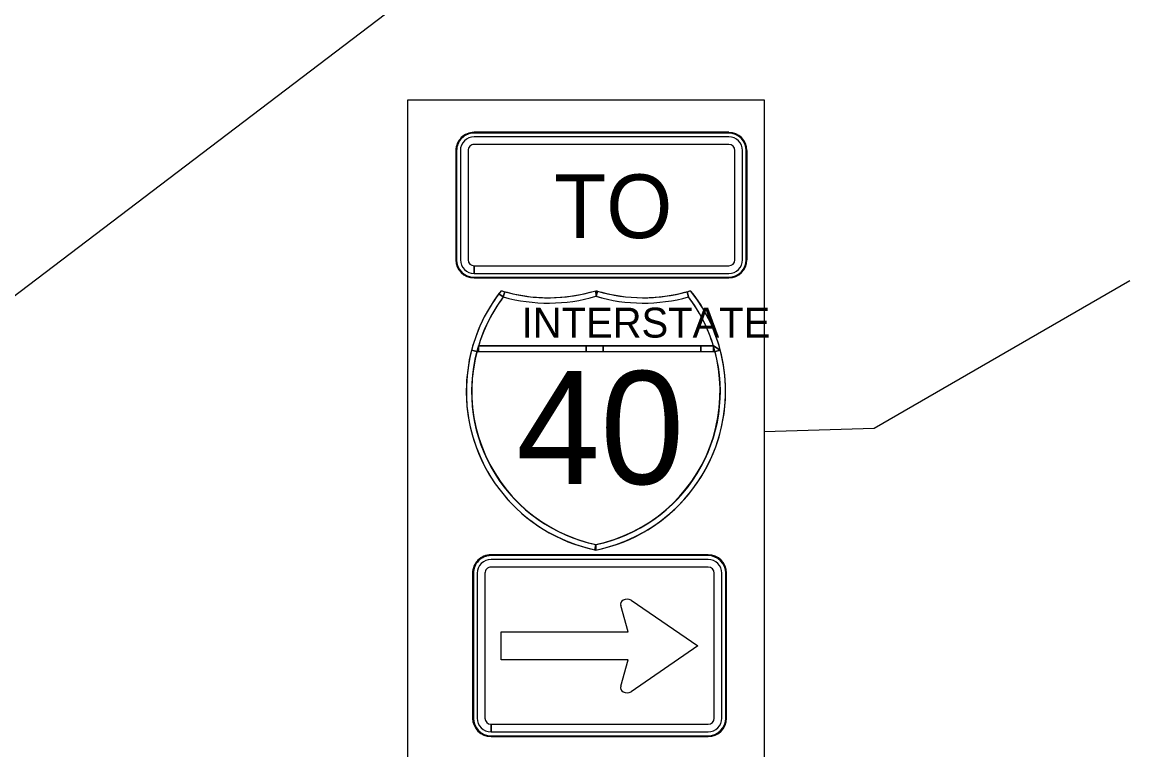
# Model space of a CAD drawing. Extents: x 886234 to 968767, y 455416 to 684046.
# Drawn here: x 914069 to 915591, y 469126 to 470126 of the extents above; entities that cross this region are included whole.
import ezdxf

# ---------------------------------------------------------------- set-up
doc = ezdxf.new("R2010")
doc.units = 0
for name, color, linetype in [('TC CONSTRUCTION PROPOSED ROADWAY SHADE', 7, 'Continuous'), ('TC DEV SIGN BLACK 239', 7, 'Continuous'), ('TC DEV SIGN BLACK ZERO', 7, 'Continuous'), ('TC DEV SIGN WHITE', 7, 'Continuous'), ('TC LABEL TEXT', 7, 'Continuous')]:
    doc.layers.add(name, color=color, linetype=linetype)

msp = doc.modelspace()

# ---------------------------------------------------------------- linework, layer by layer
at = {"layer": 'TC CONSTRUCTION PROPOSED ROADWAY SHADE'}
msp.add_lwpolyline([(914599.4, 470018.9), (915089.1, 470018.9), (915089.1, 469107.9), (914599.4, 469107.9)], close=True, dxfattribs=at)
at = {"layer": 'TC DEV SIGN BLACK 239'}
for p, q in [((915040.4, 469968.1), (914690.4, 469968.1)), ((915040.4, 469957.7), (914690.4, 469957.7)), ((914671.6, 469949.4), (914671.6, 469799.4)), ((914682.1, 469949.4), (914682.1, 469799.4)), ((915048.8, 469799.4), (915048.8, 469949.4)), ((915059.2, 469799.4), (915059.2, 469949.4)), ((914690.4, 469780.6), (914690.4, 469791.1)), ((914690.5, 469791.1), (915040.4, 469791.1)), ((914690.5, 469791.1), (914690.5, 469780.6)), ((914690.5, 469780.6), (915040.4, 469780.6)), ((915011.9, 469387.7), (914713.7, 469387.7)), ((914694.7, 469368.7), (914694.7, 469169.9)), ((914705.3, 469368.7), (914705.3, 469169.9)), ((915011.9, 469377.2), (914713.7, 469377.2)), ((915020.3, 469169.9), (915020.3, 469368.7)), ((915030.9, 469169.9), (915030.9, 469368.7)), ((914902.3, 469288.4), (914892, 469324.3)), ((914906.3, 469332), (914998, 469268.9)), ((914727.4, 469250.1), (914727.4, 469288.4)), ((914727.4, 469288.4), (914902.3, 469288.4)), ((914998, 469268.9), (914906.3, 469205.8)), ((914902.3, 469250.1), (914727.4, 469250.1)), ((914892, 469213.5), (914902.3, 469250.1)), ((914713.7, 469150.9), (914713.7, 469161.5)), ((914713.8, 469161.5), (915011.9, 469161.5)), ((914713.8, 469161.5), (914713.8, 469150.9)), ((914713.8, 469150.9), (915011.9, 469150.9))]:
    msp.add_line(p, q, dxfattribs=at)
for centre, major_axis, ratio, start_param, end_param in [((914690.4, 469949.4), (18.8, 0), 0.999865, 1.570796, 3.141593), ((914690.4, 469949.4), (8.33, 0), 0.999865, 1.570796, 3.141593), ((915040.4, 469949.4), (18.8, 0), 0.999865, 0, 1.570796), ((915040.4, 469949.4), (8.33, 0), 0.999865, 0, 1.570796), ((914690.4, 469799.4), (18.8, 0), 0.999865, 3.141593, 4.712389), ((914690.4, 469799.4), (8.33, 0), 0.999865, 3.141593, 4.712389), ((915040.4, 469799.4), (18.8, 0), 0.999865, 4.712389, 6.283185), ((915040.4, 469799.4), (8.33, 0), 0.999865, 4.712389, 6.283185), ((914713.7, 469368.7), (19, 0), 0.999865, 1.570796, 3.141593), ((915011.9, 469368.7), (19, 0), 0.999865, 0, 1.570796), ((914713.7, 469368.7), (8.45, 0), 0.999865, 1.570796, 3.141593), ((915011.9, 469368.7), (8.45, 0), 0.999865, 0, 1.570796), ((914901, 469326.4), (9.44, 0), 0.720018, 0.96961, 3.452569), ((914901, 469211.4), (9.44, 0), 0.720018, 2.830617, 5.313577), ((914713.7, 469169.9), (19, 0), 0.999865, 3.141593, 4.712389), ((914713.7, 469169.9), (8.45, 0), 0.999865, 3.141593, 4.712389), ((915011.9, 469169.9), (19, 0), 0.999865, 4.712389, 6.283185), ((915011.9, 469169.9), (8.45, 0), 0.999865, 4.712389, 6.283185)]:
    msp.add_ellipse(centre, major_axis=major_axis, ratio=ratio, start_param=start_param, end_param=end_param, dxfattribs=at)
at = {"layer": 'TC DEV SIGN BLACK ZERO'}
for p, q in [((915040.4, 469974.4), (914690.4, 469974.4)), ((914690.4, 469973.4), (914690.4, 469973.4)), ((915040.4, 469973.3), (914690.4, 469973.4)), ((915040.4, 469973.3), (915040.4, 469973.4)), ((914665.4, 469949.4), (914665.4, 469799.4)), ((914666.4, 469949.4), (914666.4, 469799.4)), ((914666.4, 469949.4), (914666.4, 469949.4)), ((915064.4, 469949.4), (915064.4, 469949.4)), ((915064.4, 469799.4), (915064.4, 469949.4)), ((915065.5, 469799.4), (915065.5, 469949.4)), ((914666.4, 469799.4), (914666.4, 469799.4)), ((915064.4, 469799.4), (915064.4, 469799.4)), ((914690.4, 469774.4), (914690.4, 469775.4)), ((914690.4, 469775.4), (914690.4, 469775.4)), ((914690.4, 469775.4), (915040.4, 469775.4)), ((914690.4, 469775.4), (914690.4, 469774.4)), ((914690.4, 469774.4), (915040.4, 469774.4)), ((915040.4, 469775.4), (915040.4, 469775.4)), ((914730.5, 469748.4), (914732.5, 469755.5)), ((914858, 469749.2), (914857.8, 469756.9)), ((914858, 469749.7), (914857.8, 469756.9)), ((914983.2, 469755.5), (914985.2, 469748.4)), ((914694.2, 469673.5), (915021.5, 469673.5)), ((914694.2, 469673.5), (914696.3, 469673.5)), ((914696.3, 469681), (915019.4, 469681)), ((914844.2, 469681), (914696.3, 469681)), ((914696.3, 469673.5), (914844.2, 469673.5)), ((914867.7, 469681), (914844.2, 469681)), ((914844.2, 469673.5), (914867.7, 469673.5)), ((915001.9, 469681), (914867.7, 469681)), ((914867.7, 469673.5), (915001.9, 469673.5)), ((915019.4, 469681), (915001.9, 469681)), ((915001.9, 469673.5), (915019.4, 469673.5)), ((915028.6, 469675.4), (915019.4, 469681)), ((915021.3, 469674), (915019.4, 469673.5)), ((915019.4, 469673.5), (915021.5, 469673.5)), ((914679.7, 469619.9), (914679.7, 469617.7)), ((915035.9, 469617.7), (915035.9, 469620)), ((915011.9, 469394.1), (914713.7, 469394.1)), ((914713.7, 469393), (914713.7, 469393)), ((915011.9, 469393), (914713.7, 469393)), ((915011.9, 469393), (915011.9, 469393)), ((914688.4, 469368.7), (914688.3, 469169.9)), ((914689.4, 469368.7), (914689.4, 469169.9)), ((914689.4, 469368.7), (914689.4, 469368.7)), ((915036.2, 469368.7), (915036.2, 469368.7)), ((915036.2, 469169.9), (915036.2, 469368.7)), ((915037.2, 469169.9), (915037.2, 469368.7)), ((914689.4, 469169.9), (914689.4, 469169.9)), ((915036.2, 469169.9), (915036.2, 469169.9)), ((914713.7, 469144.6), (914713.7, 469145.6)), ((914713.7, 469145.6), (914713.7, 469145.6)), ((914713.7, 469145.6), (915011.9, 469145.6)), ((914713.7, 469145.6), (914713.7, 469144.6)), ((914713.7, 469144.6), (915011.9, 469144.6)), ((915011.9, 469145.6), (915011.9, 469145.6))]:
    msp.add_line(p, q, dxfattribs=at)
for points in [[(914724.5, 469752.8), (914730.5, 469748.4)], [(914730.5, 469748.4), (914724.5, 469752.8)], [(914727.7, 469756.9), (914727.7, 469756.9), (914727.7, 469756.9)], [(914732.5, 469755.5), (914730.5, 469748.4)], [(914857.8, 469749.2), (914858, 469749.7)], [(914858, 469756.9), (914858, 469749.7), (914860.1, 469756.2)], [(914860.1, 469756.2), (914858, 469749.2)], [(914985.2, 469748.4), (914983.2, 469755.5)], [(914988, 469756.9), (914988, 469756.9), (914987.9, 469756.9)], [(914687, 469675.4), (914694.2, 469673.5)], [(914694.2, 469673.5), (914687, 469675.4)], [(914696.3, 469681), (914696.3, 469673.5)], [(914696.3, 469673.5), (914696.3, 469681)], [(914844.2, 469673.5), (914844.2, 469681)], [(914844.2, 469681), (914844.2, 469673.5)], [(914867.7, 469681), (914867.7, 469673.5)], [(914867.7, 469673.5), (914867.7, 469681)], [(915001.9, 469673.5), (915001.9, 469681)], [(915001.9, 469681), (915001.9, 469673.5)], [(915019.4, 469681), (915028.6, 469675.4)], [(915019.4, 469673.5), (915019.4, 469681)], [(915019.4, 469681), (915019.4, 469673.5), (915021.3, 469674), (915019.4, 469681)], [(915021.5, 469673.5), (915021.3, 469674)], [(915028.6, 469675.4), (915021.5, 469673.5)], [(915021.5, 469673.5), (915028.6, 469675.4)], [(914856.3, 469401), (914857.8, 469408.2)], [(914857.8, 469408.2), (914857.8, 469400.7)]]:
    msp.add_lwpolyline(points, dxfattribs=at)
for centre, radius, start, end in [((914902.4, 469618.8), 222.7, 141.6693, 258.4631), ((914902.4, 469618.8), 222.7, 142.9968, 165.2769), ((914902.4, 469618.8), 215.2, 142.9968, 258.0595), ((914902.4, 469618.8), 215.2, 142.9968, 165.2769), ((914902.4, 469618.8), 222.7, 141.6709, 142.9968), ((914792.8, 469969.9), 222.7, 253.0062, 286.9901), ((914792.8, 469969.9), 222.7, 253.0099, 254.2907), ((914792.8, 469969.9), 230.1, 254.2907, 286.4259), ((914792.8, 469969.9), 230.1, 254.2907, 286.4259), ((914792.8, 469969.9), 222.7, 254.2907, 286.9893), ((914922.9, 469969.9), 222.7, 253.0099, 286.9938), ((914813.3, 469618.8), 222.7, 281.5369, 38.3307), ((914922.9, 469969.9), 230.1, 253.5741, 285.7093), ((914813.3, 469618.8), 215.2, 281.9405, 37.0032), ((914922.9, 469969.9), 222.7, 253.0588, 253.6206), ((914923, 469969.5), 229.7, 253.5731, 285.7093), ((914922.9, 469969.9), 222.7, 253.6206, 285.7093), ((914922.9, 469969.9), 222.7, 285.7093, 286.9901), ((914813.3, 469618.8), 215.2, 16.7759, 37.0032), ((914813.3, 469618.8), 222.7, 14.7231, 38.3291), ((914902.4, 469618.8), 222.7, 165.2769, 179.7177), ((914901.3, 469618.2), 214.4, 165.0438, 258.3001), ((914902.4, 469618.8), 215.2, 163.2241, 165.2769), ((914814.4, 469618.2), 214.4, 281.7196, 14.964), ((914813.3, 469618.8), 215.2, 14.7231, 16.7759), ((914813.3, 469618.8), 222.7, 0.2997, 14.7231), ((914902.4, 469618.8), 222.7, 180.2823, 258.0591), ((914813.3, 469618.8), 222.7, 281.537, 359.7003), ((914813.3, 469618.8), 215.2, 281.9405, 281.9604)]:
    msp.add_arc(centre, radius, start, end, dxfattribs=at)
for centre, major_axis, start_param, end_param in [((914690.4, 469949.4), (25, 0), 1.570796, 3.141593), ((914690.4, 469949.4), (24, 0), 1.570796, 3.141593), ((915040.4, 469949.4), (25, 0), 0, 1.570796), ((915040.4, 469949.4), (24, 0), 0, 1.570796), ((914690.4, 469799.4), (25, 0), 3.141593, 4.712389), ((914690.4, 469799.4), (24, 0), 3.141593, 4.712389), ((915040.4, 469799.4), (25, 0), 4.712389, 6.283185), ((915040.4, 469799.4), (24, 0), 4.712389, 6.283185), ((914713.7, 469368.7), (25.4, 0), 1.570796, 3.141593), ((915011.9, 469368.7), (25.4, 0), 0, 1.570796), ((914713.7, 469368.7), (24.3, 0), 1.570796, 3.141593), ((915011.9, 469368.7), (24.3, 0), 0, 1.570796), ((914713.7, 469169.9), (25.4, 0), 3.141593, 4.712389), ((914713.7, 469169.9), (24.3, 0), 3.141593, 4.712389), ((915011.9, 469169.9), (25.4, 0), 4.712389, 6.283185), ((915011.9, 469169.9), (24.3, 0), 4.712389, 6.283185)]:
    msp.add_ellipse(centre, major_axis=major_axis, ratio=0.999865, start_param=start_param, end_param=end_param, dxfattribs=at)
at = {"layer": 'TC DEV SIGN WHITE'}
for p, q in [((915040.4, 469974.4), (914690.4, 469974.4)), ((914665.4, 469949.4), (914665.4, 469799.4)), ((915065.5, 469799.4), (915065.5, 469949.4)), ((914690.4, 469774.4), (915040.4, 469774.4)), ((915011.9, 469394.1), (914713.7, 469394.1)), ((914857.8, 469400.7), (914857.8, 469408.2)), ((914688.4, 469368.7), (914688.3, 469169.9)), ((915037.2, 469169.9), (915037.2, 469368.7)), ((914713.7, 469144.6), (915011.9, 469144.6))]:
    msp.add_line(p, q, dxfattribs=at)
msp.add_lwpolyline([(914857.8, 469408.2), (914856.3, 469401), (914857.8, 469400.7)], dxfattribs=at)
for centre, start, end in [((914902.4, 469618.8), 258.458, 258.463), ((914813.3, 469618.8), 281.5369590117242, 281.53700435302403)]:
    msp.add_arc(centre, 222.7, start, end, dxfattribs=at)
for centre, major_axis, start_param, end_param in [((914690.4, 469949.4), (25, 0), 1.570796, 3.141593), ((915040.4, 469949.4), (25, 0), 0, 1.570796), ((914690.4, 469799.4), (25, 0), 3.141593, 4.712389), ((915040.4, 469799.4), (25, 0), 4.712389, 6.283185), ((914713.7, 469368.7), (25.4, 0), 1.570796, 3.141593), ((915011.9, 469368.7), (25.4, 0), 0, 1.570796), ((914713.7, 469169.9), (25.4, 0), 3.141593, 4.712389), ((915011.9, 469169.9), (25.4, 0), 4.712389, 6.283185)]:
    msp.add_ellipse(centre, major_axis=major_axis, ratio=0.999865, start_param=start_param, end_param=end_param, dxfattribs=at)
at = {"layer": 'TC LABEL TEXT'}
for points in [[(913173.5, 469218.6), (913359.8, 469219.2), (914761.7, 470284.2)], [(915089.1, 469563.4), (915240, 469568), (915591.5, 469770.9)]]:
    msp.add_lwpolyline(points, dxfattribs=at)
msp.add_lwpolyline([(914599.4, 470018.9), (915089.1, 470018.9), (915089.1, 469107.9), (914599.4, 469107.9)], close=True, dxfattribs=at)

# ---------------------------------------------------------------- texts
at = {"layer": 'TC DEV SIGN BLACK 239'}
msp.add_text('TO', height=87.5, rotation=360, dxfattribs=at).set_placement((914800.4, 469829.1))
at = {"layer": 'TC DEV SIGN BLACK ZERO'}
for s, height, p in [('INTERSTATE', 41.06, (914755.8, 469692.5)), ('40', 155.13, (914748.4, 469491.3))]:
    msp.add_text(s, height=height, rotation=360, dxfattribs=at).set_placement(p)

doc.saveas('drawing.dxf')
